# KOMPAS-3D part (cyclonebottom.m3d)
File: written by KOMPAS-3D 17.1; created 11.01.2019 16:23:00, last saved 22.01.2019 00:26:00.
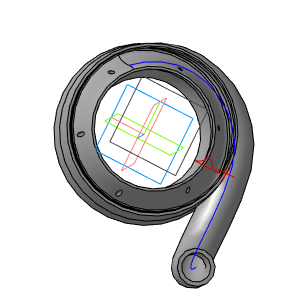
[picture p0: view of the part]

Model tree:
1. Эскиз:1
2. Элемент вращения:1
     Угол 1 = 360
3. Сплайн:2
     Координата X = -65; Координата Y = -74; Координата Z = -57; Координата X = -65; Координата Y = -48; Координата Z = -14; Вес = 1; Координата X = -65; Координата Y = -30; Координата Z = -13; Вес = 1; Координата X = -63; Координата Y = -1; Координата Z = -13; Координата X = -60; Координата Y = 12; Координата Z = -13; Координата X = -43; Координата Y = 37; Координата Z = -13; Координата X = 31; Координата Y = 35; Координата Z = -14; Порядок = 4
4. Плоскость отверстия
     Расстояние = 57
5. Профиль отверстия
6. Создаьб поверхность трубы
7. Придать толщину трубе
     Толщина стенки 1 = 3
8. Вырезать по траектории профиль трубы
9. Вырезаниеание внутри
10. Вырезать внутреннюю полость
     Угол 1 = 360
11. Вырезать циклон
     Угол 1 = 360
12. Повторно выдавить основное тело
     Угол 1 = -135
13. Крепёжные отверстия
14. Выдавить крепёжные отверстия
     Расстояние 1 = 50; Расстояние 2 = 5
15. Массив по концентрической сетке:1  (2 pattern instances)
16. Элемент выдавливания:4  (4 pattern instances)
     N 1 = 1; Шаг 1 = 10; Шаг 2 = 360; Номер 1 = 1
